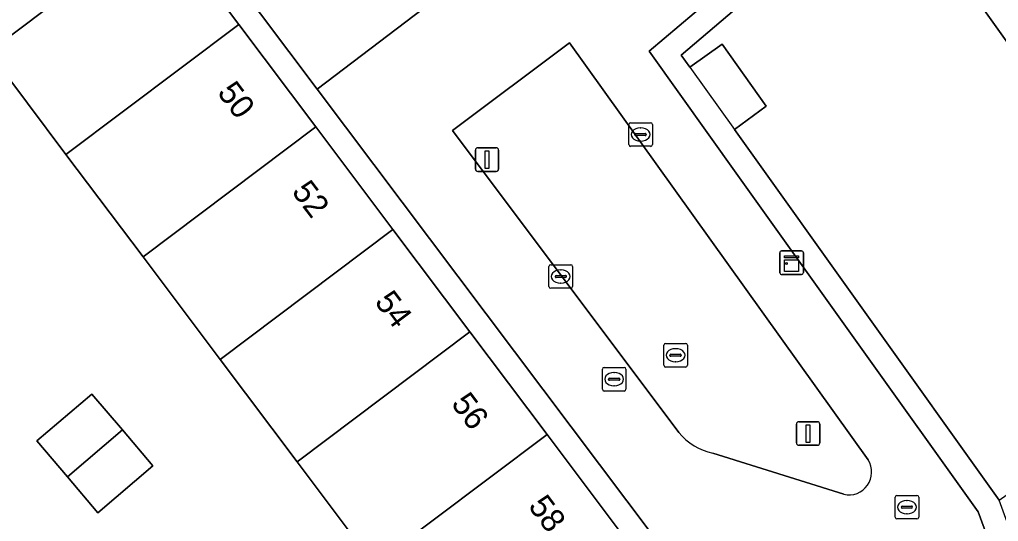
# Model space of a CAD drawing. Extents: x 160377 to 161131, y 383938 to 384853.
# Drawn here: x 160622.12 to 160663.69, y 384567.01 to 384588.32 of the extents above; entities that cross this region are included whole.
import ezdxf

# ---------------------------------------------------------------- set-up
doc = ezdxf.new("R2010")
doc.units = 0
for name, color, linetype in [('IMGEO_Erf', 7, 'Continuous'), ('IMGEO_Groenvoorziening', 7, 'Continuous'), ('IMGEO_Kast', 7, 'Continuous'), ('IMGEO_Kolk', 7, 'Continuous'), ('IMGEO_Lichtmast', 7, 'Continuous'), ('IMGEO_Pand', 7, 'Continuous'), ('IMGEO_Pand_nummerreeks', 7, 'Continuous'), ('IMGEO_Pand_overbouw', 7, 'Continuous'), ('IMGEO_Rioolput', 7, 'Continuous'), ('IMGEO_Voetgangersgebied_open', 7, 'Continuous')]:
    doc.layers.add(name, color=color, linetype=linetype)

msp = doc.modelspace()

# ---------------------------------------------------------------- linework, layer by layer
at = {"layer": 'IMGEO_Erf'}
for points in [[(160656.048, 384504.315), (160656.893, 384504.376), (160651.516, 384563.083), (160634.758, 384585.358), (160611.972, 384615.646), (160608.482, 384613.028), (160596.383, 384603.983), (160593.555, 384601.453), (160592.642, 384600.679), (160589.954, 384598.377), (160589.048, 384597.617), (160586.272, 384595.285), (160585.368, 384594.478), (160578.674, 384588.862), (160588.469, 384577.392), (160609.42, 384552.826), (160611.199, 384533.452), (160614.226, 384500.488)], [(160742.043, 384557.929), (160741.675, 384559.771), (160712.316, 384578.736), (160711.06, 384579.547), (160690.284, 384592.968), (160678.608, 384600.475), (160670.645, 384605.594), (160652.047, 384589.687), (160648.865, 384586.974), (160652.625, 384581.692), (160662.829, 384567.417), (160665.29, 384560.709), (160670.064, 384547.52), (160670.583, 384546.086), (160681.057, 384517.15), (160682.984, 384507.279), (160717.593, 384514.044), (160723.481, 384515.195), (160749.399, 384520.262)], [(160622.858, 384570.436), (160625.191, 384572.414), (160626.489, 384570.893), (160627.787, 384569.371), (160625.439, 384567.38), (160624.154, 384568.901)]]:
    msp.add_lwpolyline(points, close=True, dxfattribs=at)
for points in [[(160621.611, 384601.175), (160624.884, 384596.822), (160628.157, 384592.469), (160631.431, 384588.116), (160634.704, 384583.762), (160637.977, 384579.409), (160641.25, 384575.056), (160644.524, 384570.703), (160647.791, 384566.349), (160650.487, 384562.787), (160650.671, 384561.096), (160650.813, 384559.589), (160651.313, 384554.154), (160651.813, 384548.726), (160652.312, 384543.297), (160652.811, 384537.869), (160653.311, 384532.44)], [(160661.398, 384591.1), (160673.139, 384574.645), (160671.463, 384573.385), (160674.519, 384564.951), (160676.21, 384560.286), (160677.9, 384555.621), (160679.591, 384550.956), (160670.993, 384547.855), (160669.308, 384552.507), (160667.705, 384556.932), (160667.618, 384557.172), (160665.929, 384561.836), (160663.725, 384567.919), (160652.479, 384583.658), (160653.822, 384584.649), (160651.953, 384587.271), (160650.586, 384586.297), (160650.225, 384586.801), (160659.075, 384594.356)], [(160644.155, 384531.6), (160643.656, 384537.028), (160643.158, 384542.457), (160642.659, 384547.885), (160642.161, 384553.314), (160641.662, 384558.742), (160650.813, 384559.589), (160650.671, 384561.096), (160650.487, 384562.787), (160647.791, 384566.349), (160640.461, 384560.832), (160637.187, 384565.185), (160633.913, 384569.537), (160630.639, 384573.89), (160627.365, 384578.243), (160624.091, 384582.595), (160620.818, 384586.948)]]:
    msp.add_lwpolyline(points, dxfattribs=at)
at = {"layer": 'IMGEO_Groenvoorziening'}
for points in [[(160658.158, 384569.619), (160645.47, 384587.329), (160640.506, 384583.605), (160650.122, 384570.791)], [(160651.565, 384569.914), (160657.129, 384568.161)]]:
    msp.add_lwpolyline(points, dxfattribs=at)
for centre, radius, start, end in [((160652.067, 384572.366), 2.503, 218.9966, 258.4242), ((160657.344, 384569.102), 0.965, 257.1449, 32.4292)]:
    msp.add_arc(centre, radius, start, end, dxfattribs=at)
at = {"layer": 'IMGEO_Kast'}
for p, q in [((160654.41, 384577.571), (160654.41, 384578.412)), ((160654.41, 384578.412), (160654.41, 384577.571)), ((160654.485, 384578.496), (160655.326, 384578.496)), ((160655.326, 384578.496), (160654.485, 384578.496)), ((160655.41, 384578.421), (160655.41, 384577.58)), ((160655.41, 384577.58), (160655.41, 384578.421)), ((160655.335, 384577.496), (160654.494, 384577.496)), ((160654.494, 384577.496), (160655.335, 384577.496))]:
    msp.add_line(p, q, dxfattribs=at)
for points in [[(160654.605, 384578.286), (160655.205, 384578.286), (160655.205, 384578.201), (160654.605, 384578.201), (160654.605, 384578.286)], [(160654.605, 384578.111), (160655.205, 384578.111), (160655.205, 384577.622), (160654.605, 384577.622), (160654.605, 384578.111)]]:
    msp.add_lwpolyline(points, dxfattribs=at)
msp.add_circle((160654.689, 384577.96), 0.0377, dxfattribs=at)
for centre, start, end in [((160654.488, 384578.418), 92.4484, 184.2845), ((160654.488, 384578.418), 92.4484, 184.2845), ((160655.332, 384578.418), 2.4484, 94.2845), ((160655.332, 384578.418), 2.4484, 94.2845), ((160654.488, 384577.574), 182.4484, 274.2845), ((160654.488, 384577.574), 182.4484, 274.2845), ((160655.332, 384577.574), 272.4484, 4.2845), ((160655.332, 384577.574), 272.4484, 4.2845)]:
    msp.add_arc(centre, 0.0779, start, end, dxfattribs=at)
at = {"layer": 'IMGEO_Kolk'}
for p, q in [((160647.995, 384583.011), (160647.995, 384583.863)), ((160648.07, 384583.937), (160648.922, 384583.937)), ((160648.483, 384583.717), (160648.508, 384583.717)), ((160648.996, 384583.863), (160648.996, 384583.011)), ((160648.254, 384583.431), (160648.254, 384583.443)), ((160648.692, 384583.394), (160648.294, 384583.394)), ((160648.297, 384583.48), (160648.695, 384583.48)), ((160648.738, 384583.443), (160648.738, 384583.431)), ((160648.922, 384582.937), (160648.07, 384582.937)), ((160648.506, 384583.157), (160648.481, 384583.157)), ((160644.604, 384576.984), (160644.604, 384577.836)), ((160644.679, 384577.91), (160645.531, 384577.91)), ((160645.605, 384577.836), (160645.605, 384576.984)), ((160644.863, 384577.404), (160644.863, 384577.416)), ((160645.301, 384577.367), (160644.903, 384577.367)), ((160644.906, 384577.453), (160645.304, 384577.453)), ((160645.092, 384577.69), (160645.117, 384577.69)), ((160645.347, 384577.416), (160645.347, 384577.404)), ((160645.115, 384577.13), (160645.09, 384577.13)), ((160645.531, 384576.91), (160644.679, 384576.91)), ((160659.307, 384567.191), (160659.307, 384568.043)), ((160659.382, 384568.117), (160660.234, 384568.117)), ((160659.795, 384567.897), (160659.82, 384567.897)), ((160660.308, 384568.043), (160660.308, 384567.191)), ((160659.566, 384567.611), (160659.566, 384567.623)), ((160660.004, 384567.574), (160659.606, 384567.574)), ((160659.609, 384567.66), (160660.007, 384567.66)), ((160660.05, 384567.623), (160660.05, 384567.611)), ((160660.234, 384567.117), (160659.382, 384567.117)), ((160659.818, 384567.337), (160659.793, 384567.337))]:
    msp.add_line(p, q, dxfattribs=at)
for points in [[(160647.995, 384583.011), (160647.995, 384583.863)], [(160648.07, 384583.937), (160648.922, 384583.937)], [(160648.996, 384583.863), (160648.996, 384583.011)], [(160648.922, 384582.937), (160648.07, 384582.937)], [(160644.604, 384576.984), (160644.604, 384577.836)], [(160644.679, 384577.91), (160645.531, 384577.91)], [(160645.605, 384577.836), (160645.605, 384576.984)], [(160645.531, 384576.91), (160644.679, 384576.91)], [(160659.307, 384567.191), (160659.307, 384568.043)], [(160659.382, 384568.117), (160660.234, 384568.117)], [(160660.308, 384568.043), (160660.308, 384567.191)], [(160660.234, 384567.117), (160659.382, 384567.117)]]:
    msp.add_lwpolyline(points, dxfattribs=at)
for centre, radius, start, end in [((160648.072, 384583.861), 0.0765, 91.552, 178.448), ((160648.072, 384583.861), 0.0765, 91.552, 178.448), ((160648.92, 384583.861), 0.0765, 1.552, 88.448), ((160648.92, 384583.861), 0.0765, 1.552, 88.448), ((160648.294, 384583.44), 0.0403, 85.8775, 175.7526), ((160648.291, 384583.43), 0.0366, 178.938, 274.7102), ((160648.695, 384583.437), 0.043, 264.8664, 352.4533), ((160648.699, 384583.442), 0.0386, 1.7309, 96.639), ((160648.072, 384583.013), 0.0765, 181.552, 268.448), ((160648.072, 384583.013), 0.0765, 181.552, 268.448), ((160648.92, 384583.013), 0.0765, 271.552, 358.448), ((160648.92, 384583.013), 0.0765, 271.552, 358.448), ((160644.681, 384577.834), 0.0765, 91.552, 178.448), ((160644.681, 384577.834), 0.0765, 91.552, 178.448), ((160645.529, 384577.834), 0.0765, 1.552, 88.448), ((160645.529, 384577.834), 0.0765, 1.552, 88.448), ((160644.903, 384577.413), 0.0403, 85.8775, 175.7526), ((160644.9, 384577.403), 0.0366, 178.938, 274.7102), ((160645.304, 384577.41), 0.043, 264.8664, 352.4533), ((160645.308, 384577.415), 0.0386, 1.7309, 96.639), ((160644.681, 384576.986), 0.0765, 181.552, 268.448), ((160644.681, 384576.986), 0.0765, 181.552, 268.448), ((160645.529, 384576.986), 0.0765, 271.552, 358.448), ((160645.529, 384576.986), 0.0765, 271.552, 358.448), ((160659.384, 384568.041), 0.0765, 91.552, 178.448), ((160659.384, 384568.041), 0.0765, 91.552, 178.448), ((160660.232, 384568.041), 0.0765, 1.552, 88.448), ((160660.232, 384568.041), 0.0765, 1.552, 88.448), ((160659.606, 384567.62), 0.0403, 85.8775, 175.7526), ((160659.603, 384567.61), 0.0366, 178.938, 274.7102), ((160660.007, 384567.617), 0.043, 264.8664, 352.4533), ((160660.011, 384567.622), 0.0386, 1.7309, 96.639), ((160659.384, 384567.193), 0.0765, 181.552, 268.448), ((160659.384, 384567.193), 0.0765, 181.552, 268.448), ((160660.232, 384567.193), 0.0765, 271.552, 358.448), ((160660.232, 384567.193), 0.0765, 271.552, 358.448)]:
    msp.add_arc(centre, radius, start, end, dxfattribs=at)
for centre, major_axis, ratio, start_param, end_param in [((160648.482, 384583.437), (-0.387, 0.002), 0.722429, 4.712389, 7.853982), ((160648.507, 384583.437), (-0.39, 0.002), 0.717154, 1.570796, 4.712389), ((160645.091, 384577.41), (-0.387, 0.002), 0.722429, 4.712389, 7.853982), ((160645.116, 384577.41), (-0.39, 0.002), 0.717154, 1.570796, 4.712389), ((160659.794, 384567.617), (-0.387, 0.002), 0.722429, 4.712389, 7.853982), ((160659.819, 384567.617), (-0.39, 0.002), 0.717154, 1.570796, 4.712389)]:
    msp.add_ellipse(centre, major_axis=major_axis, ratio=ratio, start_param=start_param, end_param=end_param, dxfattribs=at)
at = {"layer": 'IMGEO_Lichtmast'}
for p, q in [((160641.477, 384581.974), (160641.477, 384582.774)), ((160641.477, 384582.774), (160641.477, 384581.974)), ((160641.577, 384582.874), (160642.367, 384582.874)), ((160642.367, 384582.874), (160641.577, 384582.874)), ((160642.467, 384582.774), (160642.467, 384581.974)), ((160642.467, 384581.974), (160642.467, 384582.774)), ((160642.367, 384581.874), (160641.577, 384581.874)), ((160641.577, 384581.874), (160642.367, 384581.874)), ((160655.112, 384570.342), (160655.112, 384571.142)), ((160655.112, 384571.142), (160655.112, 384570.342)), ((160655.212, 384571.242), (160656.002, 384571.242)), ((160656.002, 384571.242), (160655.212, 384571.242)), ((160656.102, 384571.142), (160656.102, 384570.342)), ((160656.102, 384570.342), (160656.102, 384571.142)), ((160656.002, 384570.242), (160655.212, 384570.242)), ((160655.212, 384570.242), (160656.002, 384570.242))]:
    msp.add_line(p, q, dxfattribs=at)
for points in [[(160641.897, 384582.749), (160642.047, 384582.749), (160642.047, 384581.999), (160641.897, 384581.999), (160641.897, 384582.749)], [(160655.532, 384571.117), (160655.682, 384571.117), (160655.682, 384570.367), (160655.532, 384570.367), (160655.532, 384571.117)]]:
    msp.add_lwpolyline(points, dxfattribs=at)
for centre, start, end in [((160641.577, 384582.774), 90, 180), ((160641.577, 384582.774), 90, 180), ((160642.367, 384582.774), 0, 90), ((160642.367, 384582.774), 360, 90), ((160641.577, 384581.974), 180, 270), ((160641.577, 384581.974), 180, 270), ((160642.367, 384581.974), 270, 0), ((160642.367, 384581.974), 270, 0), ((160655.212, 384571.142), 90, 180), ((160655.212, 384571.142), 90, 180), ((160656.002, 384571.142), 0, 90), ((160656.002, 384571.142), 360, 90), ((160655.212, 384570.342), 180, 270), ((160655.212, 384570.342), 180, 270), ((160656.002, 384570.342), 270, 0), ((160656.002, 384570.342), 270, 0)]:
    msp.add_arc(centre, 0.1, start, end, dxfattribs=at)
at = {"layer": 'IMGEO_Pand'}
for points in [[(160661.398, 384591.1), (160665.175, 384594.278), (160667.389, 384592.841), (160685.825, 384580.844), (160692.141, 384590.55), (160670.751, 384604.318), (160666.087, 384600.341), (160667.165, 384599.079), (160664.714, 384596.986), (160663.636, 384598.249), (160659.075, 384594.356), (160650.225, 384586.801), (160650.586, 384586.297), (160651.953, 384587.271), (160653.822, 384584.649), (160652.479, 384583.658), (160663.725, 384567.919), (160671.463, 384573.385), (160673.139, 384574.645)], [(160628.157, 384592.469), (160624.884, 384596.822), (160617.544, 384591.3), (160620.818, 384586.948)], [(160631.431, 384588.116), (160628.157, 384592.469), (160620.818, 384586.948), (160624.091, 384582.595)], [(160634.704, 384583.762), (160631.431, 384588.116), (160624.091, 384582.595), (160627.365, 384578.243)], [(160637.977, 384579.409), (160634.704, 384583.762), (160627.365, 384578.243), (160630.639, 384573.89)], [(160641.25, 384575.056), (160637.977, 384579.409), (160630.639, 384573.89), (160633.913, 384569.537)], [(160644.524, 384570.703), (160641.25, 384575.056), (160633.913, 384569.537), (160637.187, 384565.185)], [(160625.191, 384572.414), (160622.858, 384570.436), (160624.154, 384568.901), (160626.489, 384570.893)], [(160626.489, 384570.893), (160624.154, 384568.901), (160625.439, 384567.38), (160627.787, 384569.371)], [(160647.791, 384566.349), (160644.524, 384570.703), (160637.187, 384565.185), (160640.461, 384560.832)]]:
    msp.add_lwpolyline(points, close=True, dxfattribs=at)
at = {"layer": 'IMGEO_Pand_overbouw'}
msp.add_lwpolyline([(160652.479, 384583.658), (160653.822, 384584.649), (160651.953, 384587.271), (160650.586, 384586.297)], close=True, dxfattribs=at)
at = {"layer": 'IMGEO_Rioolput'}
for p, q in [((160649.481, 384573.64), (160649.481, 384574.492)), ((160649.556, 384574.566), (160650.408, 384574.566)), ((160650.482, 384574.492), (160650.482, 384573.64)), ((160649.74, 384574.06), (160649.74, 384574.072)), ((160650.178, 384574.023), (160649.78, 384574.023)), ((160649.783, 384574.109), (160650.181, 384574.109)), ((160649.969, 384574.346), (160649.994, 384574.346)), ((160650.224, 384574.072), (160650.224, 384574.06)), ((160649.992, 384573.786), (160649.967, 384573.786)), ((160646.872, 384572.622), (160646.872, 384573.474)), ((160646.947, 384573.548), (160647.799, 384573.548)), ((160647.36, 384573.328), (160647.385, 384573.328)), ((160647.873, 384573.474), (160647.873, 384572.622)), ((160650.408, 384573.566), (160649.556, 384573.566)), ((160647.131, 384573.042), (160647.131, 384573.054)), ((160647.569, 384573.005), (160647.171, 384573.005)), ((160647.174, 384573.091), (160647.572, 384573.091)), ((160647.615, 384573.054), (160647.615, 384573.042)), ((160647.799, 384572.548), (160646.947, 384572.548)), ((160647.383, 384572.768), (160647.358, 384572.768))]:
    msp.add_line(p, q, dxfattribs=at)
for points in [[(160649.481, 384573.64), (160649.481, 384574.492)], [(160649.556, 384574.566), (160650.408, 384574.566)], [(160650.482, 384574.492), (160650.482, 384573.64)], [(160646.872, 384572.622), (160646.872, 384573.474)], [(160646.947, 384573.548), (160647.799, 384573.548)], [(160647.873, 384573.474), (160647.873, 384572.622)], [(160650.408, 384573.566), (160649.556, 384573.566)], [(160647.799, 384572.548), (160646.947, 384572.548)]]:
    msp.add_lwpolyline(points, dxfattribs=at)
for centre, radius, start, end in [((160649.558, 384574.49), 0.0765, 91.552, 178.448), ((160649.558, 384574.49), 0.0765, 91.552, 178.448), ((160650.406, 384574.49), 0.0765, 1.552, 88.448), ((160650.406, 384574.49), 0.0765, 1.552, 88.448), ((160649.78, 384574.069), 0.0403, 85.8775, 175.7526), ((160649.777, 384574.059), 0.0366, 178.938, 274.7102), ((160650.181, 384574.066), 0.043, 264.8664, 352.4533), ((160650.185, 384574.071), 0.0386, 1.7309, 96.639), ((160649.558, 384573.642), 0.0765, 181.552, 268.448), ((160649.558, 384573.642), 0.0765, 181.552, 268.448), ((160650.406, 384573.642), 0.0765, 271.552, 358.448), ((160650.406, 384573.642), 0.0765, 271.552, 358.448), ((160646.949, 384573.472), 0.0765, 91.552, 178.448), ((160646.949, 384573.472), 0.0765, 91.552, 178.448), ((160647.797, 384573.472), 0.0765, 1.552, 88.448), ((160647.797, 384573.472), 0.0765, 1.552, 88.448), ((160647.171, 384573.051), 0.0403, 85.8775, 175.7526), ((160647.168, 384573.041), 0.0366, 178.938, 274.7102), ((160647.572, 384573.048), 0.043, 264.8664, 352.4533), ((160647.576, 384573.053), 0.0386, 1.7309, 96.639), ((160646.949, 384572.624), 0.0765, 181.552, 268.448), ((160646.949, 384572.624), 0.0765, 181.552, 268.448), ((160647.797, 384572.624), 0.0765, 271.552, 358.448), ((160647.797, 384572.624), 0.0765, 271.552, 358.448)]:
    msp.add_arc(centre, radius, start, end, dxfattribs=at)
for centre, major_axis, ratio, start_param, end_param in [((160649.968, 384574.066), (-0.387, 0.002), 0.722429, 4.712389, 7.853982), ((160649.993, 384574.066), (-0.39, 0.002), 0.717154, 1.570796, 4.712389), ((160647.359, 384573.048), (-0.387, 0.002), 0.722429, 4.712389, 7.853982), ((160647.384, 384573.048), (-0.39, 0.002), 0.717154, 1.570796, 4.712389)]:
    msp.add_ellipse(centre, major_axis=major_axis, ratio=ratio, start_param=start_param, end_param=end_param, dxfattribs=at)
at = {"layer": 'IMGEO_Voetgangersgebied_open'}
for points in [[(160539.968, 384717.188), (160535.283, 384723.428), (160534.832, 384724.029), (160531.839, 384722.221), (160603.494, 384626.95), (160604.071, 384626.182), (160600.544, 384623.533), (160605.23, 384617.306), (160607.339, 384614.528), (160608.482, 384613.028), (160611.972, 384615.646), (160634.758, 384585.358), (160653.945, 384599.94), (160649.862, 384602.565), (160648.502, 384603.464), (160618.749, 384622.917), (160617.41, 384623.8), (160615.335, 384625.155)], [(160665.29, 384560.709), (160662.829, 384567.417), (160652.625, 384581.692), (160648.865, 384586.974), (160652.047, 384589.687), (160670.645, 384605.594), (160672.023, 384606.761), (160670.112, 384607.993), (160669.413, 384608.444), (160666.311, 384610.443), (160664.192, 384608.65), (160662.712, 384607.424), (160653.945, 384599.94), (160634.758, 384585.358), (160651.516, 384563.083), (160656.893, 384504.376), (160660.286, 384505.11), (160659.653, 384512.586)], [(160650.122, 384570.791), (160640.506, 384583.605), (160645.47, 384587.329), (160658.158, 384569.619)], [(160657.129, 384568.161), (160651.565, 384569.914)]]:
    msp.add_lwpolyline(points, dxfattribs=at)
for centre, radius, start, end in [((160652.067, 384572.366), 2.503, 218.9966, 258.4242), ((160657.344, 384569.102), 0.965, 257.1449, 32.4292)]:
    msp.add_arc(centre, radius, start, end, dxfattribs=at)

# ---------------------------------------------------------------- texts
at = {"layer": 'IMGEO_Pand_nummerreeks'}
for s, p in [('50', (160630.487, 384585.212)), ('52', (160633.648, 384581.008)), ('54', (160637.168, 384576.326)), ('56', (160640.419, 384572.002)), ('58', (160643.692, 384567.65))]:
    msp.add_text(s, height=1, rotation=306.9384, dxfattribs=at).set_placement(p)

doc.saveas('drawing.dxf')
